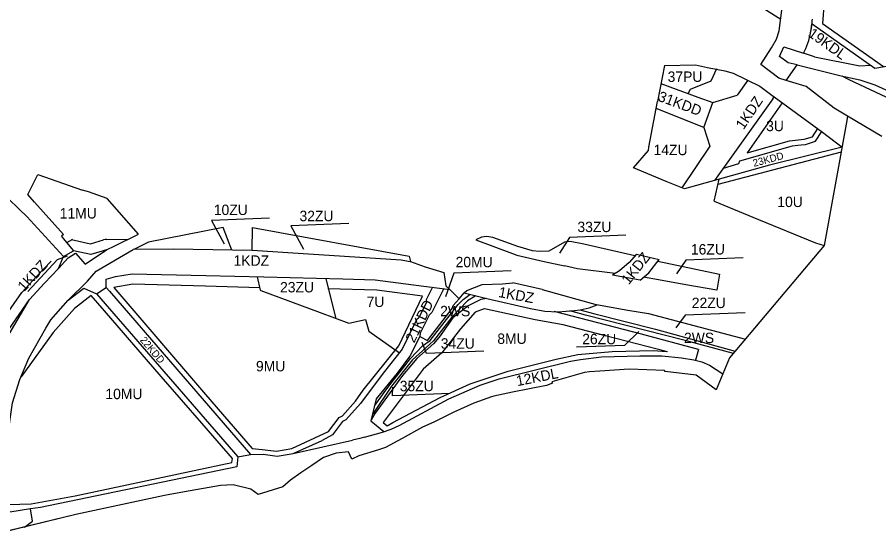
# Model space of a CAD drawing. Extents: x 7428203 to 7432868, y 5542672 to 5545406.
# Drawn here: x 7430591 to 7431420, y 5542851 to 5543351 of the extents above; entities that cross this region are included whole.
import ezdxf

# ---------------------------------------------------------------- set-up
doc = ezdxf.new("R2010")
doc.units = 0
for name, color, linetype in [('granica_planu', 7, 'Continuous'), ('linie_rozgraniczajace', 7, 'Continuous'), ('linie_zabudowy_nieprzekraczalne', 7, 'Continuous'), ('oznaczenia_przeznaczen', 7, 'Continuous')]:
    doc.layers.add(name, color=color, linetype=linetype)

msp = doc.modelspace()

# ---------------------------------------------------------------- linework, layer by layer
at = {"layer": 'granica_planu'}
msp.add_lwpolyline([(7431422.59, 5543236.25), (7431389.74, 5543255.95), (7431389.13, 5543251.74), (7431367.08, 5543131.47), (7431276.18, 5543023.34), (7431263.28, 5542992.8), (7431243.99, 5543006.85), (7431214.4, 5543010.36), (7431213.77, 5543011.39), (7431179.79, 5543012.66), (7431151.33, 5543010.71), (7431141.58, 5543010.05), (7431136.61, 5543009.28), (7431118.57, 5543004.26), (7431111.94, 5543002.21), (7431105.28, 5543000.35), (7431105.8, 5542998.99), (7431100.14, 5542996.71), (7431067.47, 5542990.3), (7431049.63, 5542986.69), (7431047.37, 5542986.02), (7431030.19, 5542979.74), (7431011.08, 5542971.03), (7431000.22, 5542965.66), (7430991.87, 5542961.42), (7430981.02, 5542956.65), (7430961.44, 5542945.84), (7430945.17, 5542937.22), (7430941.31, 5542935.94), (7430938.41, 5542934.95), (7430919.7, 5542929.09), (7430912.97, 5542926.14), (7430909.65, 5542932.97), (7430897.93, 5542931.8), (7430885.57, 5542927.74), (7430874.29, 5542920.01), (7430863.71, 5542912.75), (7430853.99, 5542905.92), (7430846.6, 5542899.22), (7430822.74, 5542892.01), (7430815.65, 5542897.26), (7430798.88, 5542901.25), (7430786.59, 5542900.57), (7430752.12, 5542894.55), (7430732.73, 5542891.16), (7430647.46, 5542872.71), (7430559.44, 5542851.36)], dxfattribs=at)
at = {"layer": 'linie_rozgraniczajace'}
for p, q in [((7431325.38, 5543348.66), (7431298.04, 5543366.23)), ((7431321.19, 5543329.86), (7431324.03, 5543337.93)), ((7431353.79, 5543334.17), (7431355.52, 5543344.49)), ((7431316.69, 5543321.39), (7431321.19, 5543329.86)), ((7431352.37, 5543328.62), (7431353.79, 5543334.17)), ((7431306.4, 5543305.6), (7431316.69, 5543321.39)), ((7431358.01, 5543312.85), (7431347.25, 5543316.46)), ((7431213.56, 5543304.68), (7431206.88, 5543269.82)), ((7431213.56, 5543304.68), (7431243.49, 5543305.15)), ((7431243.49, 5543305.15), (7431254.85, 5543302.79)), ((7431323.55, 5543292.27), (7431306.4, 5543305.6)), ((7431341.18, 5543305.28), (7431341.19, 5543305.27)), ((7431341.18, 5543305.28), (7431383.66, 5543294.77)), ((7431254.85, 5543302.79), (7431271.5, 5543299.33)), ((7431271.5, 5543299.33), (7431279.54, 5543297.28)), ((7431293.73, 5543290.32), (7431283.49, 5543276.04)), ((7431330.51, 5543290.18), (7431323.55, 5543292.27)), ((7431349.89, 5543284.33), (7431330.51, 5543290.17)), ((7431376.85, 5543263.57), (7431349.89, 5543284.33)), ((7431260, 5543268.97), (7431283.49, 5543276.04)), ((7431317.91, 5543272.57), (7431261.85, 5543194.02)), ((7431315.62, 5543277.06), (7431365.63, 5543240.49)), ((7431198.58, 5543226.16), (7431206.88, 5543269.82)), ((7431251.59, 5543245.01), (7431205.63, 5543263.2)), ((7431251.59, 5543245.01), (7431260, 5543268.97)), ((7431389.74, 5543255.95), (7431376.85, 5543263.57)), ((7431389.74, 5543255.95), (7431389.13, 5543251.74)), ((7431422.59, 5543236.25), (7431389.74, 5543255.95)), ((7431389.13, 5543251.74), (7431367.08, 5543131.47)), ((7431251.59, 5543245.01), (7431257.32, 5543227.04)), ((7431358.96, 5543231.63), (7431364.89, 5543241.03)), ((7431365.63, 5543240.49), (7431384.39, 5543225.92)), ((7431349.26, 5543228.73), (7431358.96, 5543231.63)), ((7431183.85, 5543206.02), (7431198.16, 5543222.76)), ((7431198.16, 5543222.76), (7431198.58, 5543226.16)), ((7431257.32, 5543227.04), (7431230.21, 5543187.02)), ((7431285.94, 5543212.75), (7431336.86, 5543227.45)), ((7431384.39, 5543225.92), (7431314.6, 5543208.76)), ((7431336.86, 5543227.45), (7431341.76, 5543227.85)), ((7431341.76, 5543227.85), (7431344.92, 5543228.22)), ((7431344.92, 5543228.22), (7431349.26, 5543228.73)), ((7431215.33, 5543193.01), (7431183.85, 5543206.02)), ((7431314.6, 5543208.76), (7431232.92, 5543185.93)), ((7431270.33, 5543205.9), (7431285.05, 5543210.25)), ((7431285.05, 5543210.25), (7431285.94, 5543212.75)), ((7430601.28, 5543180.63), (7430611.05, 5543199.66)), ((7430611.05, 5543199.66), (7430653.75, 5543184.51)), ((7431232.92, 5543185.93), (7431215.33, 5543193.01)), ((7431261.47, 5543174.02), (7431266.16, 5543195.22)), ((7430607.74, 5543173), (7430601.28, 5543180.63)), ((7430659.57, 5543182.95), (7430653.75, 5543184.51)), ((7430677.6, 5543176.57), (7430659.57, 5543182.95)), ((7430607.74, 5543173), (7430635.51, 5543141.93)), ((7430707.62, 5543142.34), (7430677.6, 5543176.57)), ((7430600.23, 5543159.37), (7430593.17, 5543166.03)), ((7430635.65, 5543120.86), (7430600.23, 5543159.37)), ((7430635.51, 5543141.93), (7430633.66, 5543140.45)), ((7430633.66, 5543140.45), (7430635.22, 5543138.17)), ((7430684.85, 5543131.29), (7430707.62, 5543142.34)), ((7430635.22, 5543138.17), (7430645.16, 5543126.35)), ((7430677.01, 5543127.2), (7430684.85, 5543131.29)), ((7431367.08, 5543131.47), (7431276.18, 5543023.34)), ((7430635.65, 5543120.86), (7430645.16, 5543126.35)), ((7431186.78, 5543123.21), (7431208.53, 5543117.96)), ((7430630.9, 5543109.34), (7430635.65, 5543120.86)), ((7430983.55, 5543111.1), (7430983.34, 5543111)), ((7430821.94, 5543101.35), (7430824.74, 5543088.54)), ((7430887.81, 5543099.81), (7430893.4, 5543077.69)), ((7431190.22, 5543098.15), (7431163.5, 5543103.05)), ((7430667.34, 5543085.03), (7430676.71, 5543091.03)), ((7430990.62, 5543091.31), (7430984.53, 5543079.17)), ((7431096.12, 5543089.18), (7431149.02, 5543074.34)), ((7430679.85, 5543087.55), (7430815.4, 5542930.37)), ((7430893.4, 5543077.69), (7430897.52, 5543061.36)), ((7430984.77, 5543077.03), (7430977.25, 5543061.98)), ((7430984.53, 5543079.17), (7430984.77, 5543077.03)), ((7431009.32, 5543070.83), (7431010.38, 5543073.82)), ((7431024.93, 5543073.58), (7431010.13, 5543061.85)), ((7431010.38, 5543073.82), (7431016.2, 5543080.32)), ((7431036.96, 5543079.41), (7431024.93, 5543073.58)), ((7431042.59, 5543080.43), (7431036.96, 5543079.41)), ((7431148.15, 5543074.59), (7431178.33, 5543069.24)), ((7430985.79, 5543040.06), (7431009.32, 5543070.83)), ((7431191.42, 5543046.12), (7431107.57, 5543067.9)), ((7431178.33, 5543069.24), (7431198.11, 5543066.03)), ((7431198.11, 5543066.03), (7431291.4, 5543041.44)), ((7430975.09, 5543060.13), (7430961.28, 5543031.71)), ((7430977.25, 5543061.98), (7430975.09, 5543060.13)), ((7431010.13, 5543061.85), (7430997.71, 5543044.54)), ((7430929.18, 5543049.19), (7430958.66, 5543028.39)), ((7430978.31, 5543044.01), (7430985.79, 5543040.06)), ((7430997.71, 5543044.54), (7430991.67, 5543037.29)), ((7431246.47, 5543031.32), (7431191.42, 5543046.12)), ((7430961.28, 5543031.71), (7430943.17, 5543008.79)), ((7430991.67, 5543037.29), (7430975.56, 5543022.7)), ((7431246.47, 5543031.32), (7431243.36, 5543021.07)), ((7430975.56, 5543022.7), (7430961.55, 5543006.48)), ((7431276.18, 5543023.34), (7431263.28, 5542992.8)), ((7430961.55, 5543006.48), (7430935.2, 5542970.07)), ((7431136.61, 5543009.28), (7431118.57, 5543004.26)), ((7431141.58, 5543010.05), (7431136.61, 5543009.28)), ((7431151.33, 5543010.71), (7431141.58, 5543010.05)), ((7431179.79, 5543012.66), (7431151.33, 5543010.71)), ((7431213.77, 5543011.39), (7431179.79, 5543012.66)), ((7431214.4, 5543010.36), (7431213.77, 5543011.39)), ((7431243.99, 5543006.85), (7431214.4, 5543010.36)), ((7431263.28, 5542992.8), (7431243.99, 5543006.85)), ((7431105.8, 5542998.99), (7431100.14, 5542996.71)), ((7431111.94, 5543002.21), (7431105.28, 5543000.35)), ((7431105.28, 5543000.35), (7431105.8, 5542998.99)), ((7431118.57, 5543004.26), (7431111.94, 5543002.21)), ((7431067.47, 5542990.3), (7431049.63, 5542986.69)), ((7431100.14, 5542996.71), (7431067.47, 5542990.3)), ((7431047.37, 5542986.02), (7431030.19, 5542979.74)), ((7431049.63, 5542986.69), (7431047.37, 5542986.02)), ((7431030.19, 5542979.74), (7431011.08, 5542971.03)), ((7430935.2, 5542970.07), (7430931.42, 5542963.5)), ((7431000.22, 5542965.66), (7430991.87, 5542961.42)), ((7431011.08, 5542971.03), (7431000.22, 5542965.66)), ((7430981.02, 5542956.65), (7430961.44, 5542945.84)), ((7430991.87, 5542961.42), (7430981.02, 5542956.65)), ((7430894.31, 5542949.4), (7430884.44, 5542943.89)), ((7430856.36, 5542931.3), (7430913.61, 5542944.4)), ((7430856.36, 5542931.3), (7430884.44, 5542943.89)), ((7430920.71, 5542945.93), (7430913.61, 5542944.4)), ((7430925.14, 5542947.16), (7430920.71, 5542945.93)), ((7430961.44, 5542945.84), (7430945.17, 5542937.22)), ((7430897.93, 5542931.8), (7430885.57, 5542927.74)), ((7430909.65, 5542932.97), (7430897.93, 5542931.8)), ((7430912.97, 5542926.14), (7430909.65, 5542932.97)), ((7430938.41, 5542934.95), (7430919.7, 5542929.09)), ((7430941.31, 5542935.94), (7430938.41, 5542934.95)), ((7430945.17, 5542937.22), (7430941.31, 5542935.94)), ((7430803.34, 5542928.16), (7430815.4, 5542930.37)), ((7430815.4, 5542930.37), (7430827.74, 5542930.92)), ((7430827.74, 5542930.92), (7430841.19, 5542928.82)), ((7430841.19, 5542928.82), (7430856.36, 5542931.3)), ((7430885.57, 5542927.74), (7430874.29, 5542920.01)), ((7430919.7, 5542929.09), (7430912.97, 5542926.14)), ((7430874.29, 5542920.01), (7430863.71, 5542912.75)), ((7430863.71, 5542912.75), (7430853.99, 5542905.92)), ((7430786.59, 5542900.57), (7430752.12, 5542894.55)), ((7430798.88, 5542901.25), (7430786.59, 5542900.57)), ((7430815.65, 5542897.26), (7430798.88, 5542901.25)), ((7430846.6, 5542899.22), (7430822.74, 5542892.01)), ((7430853.99, 5542905.92), (7430846.6, 5542899.22)), ((7430732.73, 5542891.16), (7430647.46, 5542872.71)), ((7430752.12, 5542894.55), (7430732.73, 5542891.16)), ((7430822.74, 5542892.01), (7430815.65, 5542897.26)), ((7430647.46, 5542872.71), (7430559.44, 5542851.36))]:
    msp.add_line(p, q, dxfattribs=at)
for points in [[(7431324.03, 5543337.93), (7431326.85, 5543360.24), (7431328.85, 5543390.18)], [(7431355.55, 5543344.75), (7431415.94, 5543301.93)], [(7431341.18, 5543305.28), (7431332.65, 5543306.96), (7431324.08, 5543313.32), (7431328.38, 5543322.38), (7431347.25, 5543316.46)], [(7431347.25, 5543316.46), (7431349.6, 5543320.92), (7431352.37, 5543328.62)], [(7431415.94, 5543301.93), (7431436.35, 5543305.54), (7431463.65, 5543312.41), (7431492.57, 5543328.57), (7431547.32, 5543289.35), (7431547.5, 5543281)], [(7431358.01, 5543312.85), (7431401.47, 5543304.12), (7431411.95, 5543304.76)], [(7431330.51, 5543290.17), (7431341.18, 5543305.28)], [(7431279.54, 5543297.28), (7431305.18, 5543284.7), (7431315.62, 5543277.06)], [(7431383.66, 5543294.77), (7431401.55, 5543290.86), (7431416.06, 5543285.83), (7431464.51, 5543263.85), (7431478.05, 5543260.69), (7431487.44, 5543259.4)], [(7431384.15, 5543294.67), (7431390.98, 5543291.05), (7431457.43, 5543259.96)], [(7431210.22, 5543287.25), (7431245.79, 5543274.19), (7431260, 5543268.97)], [(7431317.91, 5543272.57), (7431319.24, 5543274.42)], [(7430532.69, 5543191.3), (7430581.89, 5543176.93), (7430593.17, 5543166.03)], [(7431261.47, 5543174.02), (7431304.04, 5543156.49), (7431358.91, 5543134.14), (7431367.08, 5543131.47)], [(7430797.41, 5543127.03), (7430789.08, 5543148.63), (7430717.22, 5543134.56), (7430703.28, 5543127.55)], [(7430817.05, 5543126.67), (7430817.5, 5543148.92), (7430967.97, 5543121.29), (7430969.19, 5543115.92), (7430983.55, 5543111.1)], [(7431185.13, 5543121.38), (7431136.14, 5543132.76), (7431122.82, 5543135.29), (7431117.5, 5543134.55), (7431102.38, 5543125.96), (7431093.26, 5543125.56), (7431086.75, 5543126.47), (7431072.47, 5543130.6), (7431048.41, 5543139.12), (7431042.77, 5543140.18), (7431037.51, 5543139.55), (7431032.17, 5543136.76), (7431067.51, 5543123.71)], [(7430630.9, 5543109.34), (7430640.21, 5543119.63), (7430647.09, 5543124.22)], [(7430640.04, 5543078.8), (7430658.82, 5543097.28), (7430666.9, 5543106.9), (7430702.7, 5543127.54)], [(7430677.01, 5543127.2), (7430669.48, 5543124.99), (7430661.95, 5543122.77), (7430645.16, 5543126.35)], [(7430647.09, 5543124.22), (7430656.36, 5543113.5), (7430677.01, 5543127.2)], [(7430970.76, 5543115.39), (7430960.39, 5543117.22), (7430851.24, 5543124.43), (7430817.52, 5543126.66), (7430817.05, 5543126.67), (7430741.53, 5543128.06), (7430702.7, 5543127.54)], [(7431067.51, 5543123.71), (7431071.7, 5543122.2), (7431098.03, 5543116.18), (7431117.41, 5543111.93)], [(7431186.78, 5543123.21), (7431179.59, 5543115.24), (7431170.41, 5543107.24), (7431163.5, 5543103.05)], [(7431190.22, 5543098.15), (7431198.61, 5543105.32), (7431208.53, 5543117.96)], [(7431207.19, 5543116.25), (7431266.4, 5543103.96), (7431263.97, 5543088.4), (7431234.21, 5543093.57), (7431207.77, 5543098.32), (7431193.41, 5543100.88)], [(7430630.9, 5543109.34), (7430617.2, 5543095.14), (7430602.9, 5543079.56)], [(7430983.34, 5543111), (7431001.31, 5543105.39), (7431003.25, 5543092.61), (7431007.1, 5543089.25)], [(7431166.06, 5543104.6), (7431129.89, 5543109.1), (7431117.41, 5543111.93)], [(7430679.85, 5543087.55), (7430676.71, 5543091.03), (7430676.51, 5543098.98), (7430685.45, 5543101.53), (7430701.58, 5543104.29), (7430772.34, 5543102.49)], [(7430772.34, 5543102.49), (7430828.15, 5543101.21), (7430904.17, 5543099.42), (7430935.38, 5543098.34), (7430972.06, 5543093.63), (7431007.1, 5543089.25)], [(7431001.41, 5543089.96), (7430989.76, 5543067.08), (7430987.26, 5543064.33), (7430978.78, 5543047.23), (7430978.41, 5543044.22), (7430969.4, 5543026.05), (7430956.42, 5543008.56), (7430936.4, 5542983.96), (7430931.26, 5542962.87), (7430943.63, 5542952.43)], [(7431007.1, 5543089.25), (7431016.2, 5543080.32), (7431020.97, 5543085.89)], [(7431020.97, 5543085.89), (7431023.39, 5543088.32), (7431038.38, 5543094.04), (7431057.86, 5543094.64), (7431067.68, 5543095.64)], [(7431096.12, 5543089.18), (7431067.68, 5543095.64)], [(7430824.74, 5543088.54), (7430825.32, 5543088.32), (7430882.47, 5543066.96), (7430909.9, 5543056.76)], [(7431032.15, 5543083.02), (7431031.49, 5543082.8), (7431024.11, 5543078.22), (7431009.22, 5543062.48), (7430991.34, 5543039.66), (7430980.73, 5543030.07), (7430971.11, 5543021.38), (7430951.1, 5542996.28), (7430932.76, 5542969)], [(7430934.89, 5542977.75), (7430943.98, 5542990.11), (7430949.36, 5542997.43), (7430961.57, 5543012.9), (7430969.35, 5543022.76), (7430980.93, 5543034.86), (7430988.13, 5543040.13), (7431001.57, 5543057.3), (7431011.01, 5543069.36), (7431015.2, 5543074.71), (7431019.97, 5543079.64), (7431026.4, 5543084.28), (7431026.64, 5543084.4)], [(7431020.91, 5543085.82), (7431042.59, 5543080.43), (7431084.62, 5543070.77), (7431098.68, 5543068.41), (7431110.93, 5543067.71), (7431127, 5543068.88), (7431132.51, 5543069.6), (7431141.19, 5543071.49), (7431149.02, 5543074.34)], [(7430539.24, 5542989.88), (7430556.31, 5543012.63), (7430602.9, 5543079.56)], [(7430539.24, 5542989.88), (7430557.16, 5542950.48), (7430563.6, 5542992.83), (7430564.95, 5543001.72), (7430577.95, 5543036.88), (7430602.9, 5543079.56)], [(7431279.87, 5543027.73), (7431233.58, 5543040.14), (7431137.74, 5543064.42), (7431122.53, 5543068.55)], [(7431132.25, 5543069.57), (7431146.49, 5543065.7), (7431205.07, 5543051.02), (7431281.63, 5543029.82)], [(7430909.9, 5543056.76), (7430926.03, 5543060.4), (7430929.18, 5543049.19)], [(7430925.14, 5542947.16), (7430942.4, 5542951.98), (7430950.72, 5542954.98), (7430958.32, 5542958.46), (7431006.2, 5542984.06), (7431036.32, 5542997.13), (7431054.65, 5543003.21), (7431123.37, 5543020.34), (7431132.91, 5543021.98), (7431152.9, 5543024.33), (7431189.8, 5543025.51), (7431211.08, 5543025.27), (7431229.97, 5543023.49), (7431241.8, 5543021.48), (7431249.57, 5543019.43), (7431256.95, 5543016.4), (7431269.79, 5543008.2)], [(7430943.17, 5543008.79), (7430943.12, 5543008.61), (7430921.15, 5542979.67), (7430907.13, 5542963.77), (7430903.98, 5542962.06), (7430894.31, 5542949.4)], [(7430598.07, 5542860.73), (7430605.65, 5542866.37), (7430603.73, 5542878.38)]]:
    msp.add_lwpolyline(points, dxfattribs=at)
msp.add_lwpolyline([(7430802.24, 5542918.55), (7430613.59, 5542879.57), (7430603.73, 5542878.38), (7430583.89, 5542874.93), (7430579.15, 5542914.59), (7430581.28, 5542943.83), (7430586.64, 5542980.02), (7430593.65, 5543002.63), (7430602.22, 5543023.27), (7430618.72, 5543051.98), (7430623.29, 5543059.94), (7430640.04, 5543078.8), (7430655.04, 5543090.28), (7430667.34, 5543085.03), (7430803.34, 5542928.16)], close=True, dxfattribs=at)
msp.add_ellipse((7431131.75, 5543374.32), major_axis=(0, 234.8609), ratio=0.96016431, start_param=4.54608009, end_param=4.6049179, dxfattribs=at)
at = {"layer": 'linie_zabudowy_nieprzekraczalne'}
for p, q in [((7431365.58, 5543344.99), (7431424.16, 5543303.46)), ((7431326.92, 5543268.8), (7431292.99, 5543220.43)), ((7431383.47, 5543221.23), (7431265.07, 5543189.99)), ((7430638.77, 5543134.2), (7430644.42, 5543137.46)), ((7430676.88, 5543137.2), (7430697.6, 5543137.48)), ((7430610, 5543102.09), (7430623.71, 5543116.28)), ((7430595.53, 5543086.32), (7430609.83, 5543101.9)), ((7430958.13, 5543034.82), (7430980.89, 5543082.72)), ((7430943.05, 5542961.3), (7430946.81, 5542957.94))]:
    msp.add_line(p, q, dxfattribs=at)
for points in [[(7431371.53, 5543495.49), (7431369.17, 5543476.66), (7431369.05, 5543442.73), (7431368.76, 5543387.51), (7431365.58, 5543344.99)], [(7431236.48, 5543277.61), (7431238.49, 5543281.87), (7431258.66, 5543289.72), (7431264.03, 5543301.76)], [(7431292.99, 5543220.43), (7431333.96, 5543232.21), (7431347.95, 5543233.61), (7431355.97, 5543236.01), (7431361.15, 5543244.02)], [(7430643.15, 5543137.19), (7430661.56, 5543133.08), (7430674.19, 5543136.8)], [(7430772.09, 5543092.5), (7430702.31, 5543094.27), (7430683.97, 5543091.13)], [(7430683.97, 5543091.13), (7430772.25, 5542988.26), (7430816.89, 5542936.24), (7430826.75, 5542935.3), (7430840.39, 5542933.76), (7430855.19, 5542936.17), (7430890.34, 5542952.44), (7430900.65, 5542965.94), (7430903.97, 5542967.74), (7430916.33, 5542981.72), (7430923.68, 5542992.47), (7430958.11, 5543034.86)], [(7430823.98, 5543090.87), (7430772.11, 5543092.5)], [(7430980.89, 5543082.72), (7430936.81, 5543088.55), (7430889.67, 5543089.76)], [(7430534.59, 5543000.35), (7430548.21, 5543018.49), (7430595.53, 5543086.32)], [(7430582.67, 5542882.44), (7430604.39, 5542882.87), (7430646.89, 5542890.7), (7430761.21, 5542915.18), (7430797.42, 5542922.66), (7430798.11, 5542926.47), (7430768.53, 5542960.68), (7430729.57, 5543005.62), (7430675.05, 5543068.5), (7430662.1, 5543083.43)], [(7430662.31, 5543083.39), (7430646.07, 5543070.77), (7430625.77, 5543047.86), (7430594.73, 5543005.07)], [(7431040.24, 5543070.71), (7431031.64, 5543067.47), (7431017.28, 5543051.28), (7430999.44, 5543028.12), (7430981.61, 5543012.38), (7430943.02, 5542961.14)], [(7431116.08, 5543055.25), (7431089.24, 5543059.89), (7431040.36, 5543070.47)], [(7431216.49, 5543029.32), (7431156.97, 5543044.69), (7431116.08, 5543055.25)], [(7430946.74, 5542958), (7430952.21, 5542961.16), (7430998.01, 5542985.35), (7431026.59, 5542998.36), (7431063.22, 5543010.58), (7431109.42, 5543022.1), (7431130.33, 5543026.61), (7431163.22, 5543029.66), (7431202.76, 5543030.36), (7431215.89, 5543029.48)]]:
    msp.add_lwpolyline(points, dxfattribs=at)
for centre, radius, start, end in [((7430677.0188, 5543127.0212), 10.1798, 90.7814562, 106.1342313), ((7430594.525, 5543115.765), 20.6514, 317.826157, 318.5335033)]:
    msp.add_arc(centre, radius, start, end, dxfattribs=at)
at = {"layer": 'oznaczenia_przeznaczen'}
for points in [[(7430833.66, 5543157.71), (7430777.9, 5543155.44), (7430789.97, 5543133.19)], [(7430910.03, 5543152.51), (7430854.27, 5543150.25), (7430866.34, 5543128)], [(7431176.46, 5543141.31), (7431122.26, 5543139.11), (7431112.6, 5543124.09)], [(7430639.05, 5543121.1), (7430629.58, 5543117.83), (7430601.38, 5543087.24)], [(7431289.24, 5543119.74), (7431234.21, 5543117.5), (7431225.29, 5543104.09)], [(7431066.07, 5543106.97), (7431011.02, 5543104.73), (7431002.96, 5543082.18)], [(7431291.32, 5543066.84), (7431233.48, 5543064.5), (7431224.43, 5543052.18)], [(7431129.06, 5543033.86), (7431175.34, 5543035.74), (7431189.08, 5543048.91)], [(7431039.78, 5543029.7), (7430984.73, 5543027.46), (7430980.47, 5543038.11)], [(7431007.17, 5542989.06), (7430952.12, 5542986.83), (7430952.49, 5542995.15)]]:
    msp.add_lwpolyline(points, dxfattribs=at)

# ---------------------------------------------------------------- texts
for s, height, rotation, p in [('19KDL', 10, 324.419905, (7431350.9652, 5543333.3303)), ('31KDD', 10, 339.6357207, (7431206.6059, 5543270.8634)), ('1KDZ', 10, 56.0981926, (7431289.6343, 5543242.2062)), ('23KDD', 7, 15.0002222, (7431299.6341, 5543207.0291)), ('1KDZ', 10, 359.7657039, (7430799.1205, 5543112.0451)), ('1KDZ', 10, 51.421161, (7431179.1848, 5543093.0601)), ('1KDZ', 10, 47.5820143, (7430597.7982, 5543086.5498)), ('1KDZ', 10, 349.7219167, (7431053.4022, 5543081.9896)), ('21KDD', 10, 64.0213634, (7430972.8777, 5543037.207)), ('22KDD', 7, 310.5239568, (7430708.7003, 5543040.1823)), ('12KDL', 10, 11.2067732, (7431072.0865, 5542996.1363))]:
    msp.add_text(s, height=height, rotation=rotation, dxfattribs=at).set_placement(p)
for s, p in [('37PU', (7431216.6428, 5543288.8)), ('3U', (7431311.3541, 5543241.4)), ('14ZU', (7431203.0828, 5543218.35)), ('10U', (7431322.1309, 5543168.44)), ('11MU', (7430631.9432, 5543157.41)), ('10ZU', (7430780.1428, 5543160.76)), ('32ZU', (7430862.5628, 5543154.84)), ('33ZU', (7431129.8828, 5543144.36)), ('16ZU', (7431239.0228, 5543122.77)), ('20MU', (7431012.6832, 5543110.54)), ('23ZU', (7430843.8528, 5543086.35)), ('7U', (7430927.0941, 5543072.32)), ('22ZU', (7431239.8428, 5543071.29)), ('2WS', (7430997.8359, 5543063.41)), ('2WS', (7431232.3659, 5543037.64)), ('34ZU', (7430998.4528, 5543032.26)), ('8MU', (7431052.8264, 5543036.84)), ('26ZU', (7431134.4928, 5543036.51)), ('9MU', (7430820.7064, 5543010.42)), ('35ZU', (7430958.9928, 5542991.34)), ('10MU', (7430675.8832, 5542983.71))]:
    msp.add_text(s, height=10, dxfattribs=at).set_placement(p)

doc.saveas('drawing.dxf')
